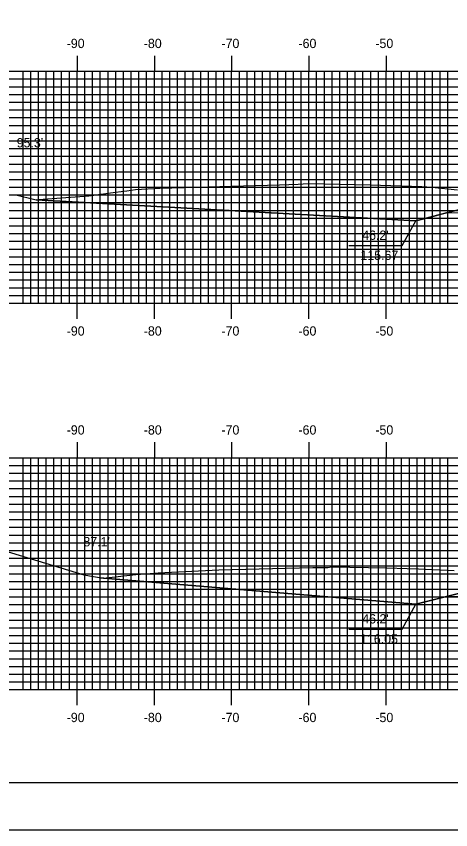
# Model space of a CAD drawing. Extents: x 854681 to 855024, y 366605 to 366825.
# Drawn here: x 854748.7 to 854804.9, y 366604.9 to 366710.2 of the extents above; entities that cross this region are included whole.
import ezdxf

# ---------------------------------------------------------------- set-up
doc = ezdxf.new("R2010")
doc.units = 0
for name, color, linetype in [('ANNOTATION', 7, 'Continuous'), ('BORDER', 7, 'Continuous'), ('D_Drainage_Underdrain', 7, 'Continuous'), ('D_Roadway_Centerline', 7, 'Continuous'), ('D_Roadway_SlopeLines', 7, 'Continuous'), ('D_Roadway_SubGrade', 7, 'Continuous'), ('D_Text_Standard', 7, 'Continuous'), ('H_V ANNOTATION', 7, 'Continuous'), ('M_Roadway_Centerline', 7, 'Continuous'), ('MAJOR', 7, 'Continuous'), ('MINOR', 7, 'Continuous'), ('PLOT BOUNDARY', 7, 'Continuous'), ('S_Roadway_Centerline', 7, 'Continuous')]:
    doc.layers.add(name, color=color, linetype=linetype)

msp = doc.modelspace()

# ---------------------------------------------------------------- linework, layer by layer
at = {"layer": 'ANNOTATION'}
for points in [[(854804.38, 366684.73), (854800.38, 366683.73), (854751.25, 366686.43)], [(854791.72, 366680.52), (854798.65, 366680.52), (854800.38, 366683.73)], [(854791.72, 366630.89), (854798.65, 366630.89), (854800.38, 366634.1)]]:
    msp.add_lwpolyline(points, dxfattribs=at)
at = {"layer": 'BORDER'}
msp.add_lwpolyline([(854696.96, 366611.06), (855016.96, 366611.06), (855016.96, 366821.06), (854696.96, 366821.06)], close=True, dxfattribs=at)
at = {"layer": 'D_Drainage_Underdrain'}
msp.add_lwpolyline([(854804.38, 366635.1), (854800.38, 366634.1), (854759.48, 366637.54)], dxfattribs=at)
at = {"layer": 'D_Roadway_Centerline'}
for points in [[(854751.25, 366686.43), (854751.26, 366686.43), (854800.38, 366683.73), (854802.76, 366684.32), (854803.66, 366684.55), (854810.24, 366686.2), (854814.56, 366687.27), (854816.02, 366687.33), (854822.55, 366687.59), (854822.56, 366687.59), (854822.56, 366687.59), (854834.56, 366687.83), (854846.56, 366688.07), (854848.89, 366687.99), (854850.56, 366687.92), (854851.62, 366687.78), (854854.63, 366687.37)], [(854759.48, 366637.54), (854759.49, 366637.54), (854800.38, 366634.1), (854803.66, 366634.92), (854803.66, 366634.92), (854814.56, 366637.65), (854814.56, 366637.65), (854818.67, 366637.81), (854822.56, 366637.97), (854834.55, 366638.21), (854834.56, 366638.21), (854846.55, 366638.45), (854846.56, 366638.45), (854850.56, 366638.29), (854852.3, 366638.08), (854855.81, 366637.66)]]:
    msp.add_lwpolyline(points, dxfattribs=at)
at = {"layer": 'D_Roadway_SlopeLines'}
for p, q in [((854814.56, 366687.27), (854800.38, 366683.73)), ((854800.38, 366683.73), (854751.25, 366686.43)), ((854800.38, 366634.1), (854759.48, 366637.54)), ((854814.56, 366637.65), (854800.38, 366634.1))]:
    msp.add_line(p, q, dxfattribs=at)
at = {"layer": 'D_Roadway_SubGrade'}
for points in [[(854822.56, 366686.93), (854822.56, 366687.34), (854814.56, 366687.02), (854814.56, 366687.27), (854804.38, 366684.73), (854822.56, 366685.09)], [(854822.56, 366637.3), (854822.56, 366637.72), (854814.56, 366637.4), (854814.56, 366637.65), (854804.38, 366635.1), (854822.56, 366635.47)]]:
    msp.add_lwpolyline(points, close=True, dxfattribs=at)
at = {"layer": 'MAJOR'}
for p, q in [((854756.56, 366705.06), (854756.56, 366703.06)), ((854766.56, 366705.06), (854766.56, 366703.06)), ((854776.56, 366705.06), (854776.56, 366703.06)), ((854786.56, 366705.06), (854786.56, 366703.06)), ((854796.56, 366705.06), (854796.56, 366703.06)), ((854706.56, 366703.06), (854986.56, 366703.06)), ((854706.56, 366703.06), (854986.56, 366703.06)), ((854756.56, 366673.06), (854756.56, 366703.06)), ((854766.56, 366673.06), (854766.56, 366703.06)), ((854776.56, 366673.06), (854776.56, 366703.06)), ((854786.56, 366673.06), (854786.56, 366703.06)), ((854796.56, 366673.06), (854796.56, 366703.06)), ((854706.56, 366698.06), (854986.56, 366698.06)), ((854706.56, 366693.06), (854986.56, 366693.06)), ((854706.56, 366688.06), (854986.56, 366688.06)), ((854706.56, 366683.06), (854986.56, 366683.06)), ((854706.56, 366678.06), (854986.56, 366678.06)), ((854706.56, 366673.06), (854986.56, 366673.06)), ((854706.56, 366673.06), (854986.56, 366673.06)), ((854756.56, 366671.05), (854756.56, 366673.06)), ((854766.56, 366671.05), (854766.56, 366673.06)), ((854776.56, 366671.05), (854776.56, 366673.06)), ((854786.56, 366671.05), (854786.56, 366673.06)), ((854796.56, 366671.05), (854796.56, 366673.06)), ((854756.56, 366655.06), (854756.56, 366653.06)), ((854766.56, 366655.06), (854766.56, 366653.06)), ((854776.56, 366655.06), (854776.56, 366653.06)), ((854786.56, 366655.06), (854786.56, 366653.06)), ((854796.56, 366655.06), (854796.56, 366653.06)), ((854706.56, 366653.06), (854986.56, 366653.06)), ((854706.56, 366653.06), (854986.56, 366653.06)), ((854756.56, 366623.06), (854756.56, 366653.06)), ((854766.56, 366623.06), (854766.56, 366653.06)), ((854776.56, 366623.06), (854776.56, 366653.06)), ((854786.56, 366623.06), (854786.56, 366653.06)), ((854796.56, 366623.06), (854796.56, 366653.06)), ((854706.56, 366648.06), (854986.56, 366648.06)), ((854706.56, 366643.06), (854986.56, 366643.06)), ((854706.56, 366638.06), (854986.56, 366638.06)), ((854706.56, 366633.06), (854986.56, 366633.06)), ((854706.56, 366628.06), (854986.56, 366628.06)), ((854706.56, 366623.06), (854986.56, 366623.06)), ((854706.56, 366623.06), (854986.56, 366623.06)), ((854756.56, 366621.05), (854756.56, 366623.06)), ((854766.56, 366621.05), (854766.56, 366623.06)), ((854776.56, 366621.05), (854776.56, 366623.06)), ((854786.56, 366621.05), (854786.56, 366623.06)), ((854796.56, 366621.05), (854796.56, 366623.06))]:
    msp.add_line(p, q, dxfattribs=at)
at = {"layer": 'MINOR'}
for p, q in [((854749.56, 366673.06), (854749.56, 366703.06)), ((854750.56, 366673.06), (854750.56, 366703.06)), ((854751.56, 366673.06), (854751.56, 366703.06)), ((854752.56, 366673.06), (854752.56, 366703.06)), ((854753.56, 366673.06), (854753.56, 366703.06)), ((854754.56, 366673.06), (854754.56, 366703.06)), ((854755.56, 366673.06), (854755.56, 366703.06)), ((854757.56, 366673.06), (854757.56, 366703.06)), ((854758.56, 366673.06), (854758.56, 366703.06)), ((854759.56, 366673.06), (854759.56, 366703.06)), ((854760.56, 366673.06), (854760.56, 366703.06)), ((854761.56, 366673.06), (854761.56, 366703.06)), ((854762.56, 366673.06), (854762.56, 366703.06)), ((854763.56, 366673.06), (854763.56, 366703.06)), ((854764.56, 366673.06), (854764.56, 366703.06)), ((854765.56, 366673.06), (854765.56, 366703.06)), ((854767.56, 366673.06), (854767.56, 366703.06)), ((854768.56, 366673.06), (854768.56, 366703.06)), ((854769.56, 366673.06), (854769.56, 366703.06)), ((854770.56, 366673.06), (854770.56, 366703.06)), ((854771.56, 366673.06), (854771.56, 366703.06)), ((854772.56, 366673.06), (854772.56, 366703.06)), ((854773.56, 366673.06), (854773.56, 366703.06)), ((854774.56, 366673.06), (854774.56, 366703.06)), ((854775.56, 366673.06), (854775.56, 366703.06)), ((854777.56, 366673.06), (854777.56, 366703.06)), ((854778.56, 366673.06), (854778.56, 366703.06)), ((854779.56, 366673.06), (854779.56, 366703.06)), ((854780.56, 366673.06), (854780.56, 366703.06)), ((854781.56, 366673.06), (854781.56, 366703.06)), ((854782.56, 366673.06), (854782.56, 366703.06)), ((854783.56, 366673.06), (854783.56, 366703.06)), ((854784.56, 366673.06), (854784.56, 366703.06)), ((854785.56, 366673.06), (854785.56, 366703.06)), ((854787.56, 366673.06), (854787.56, 366703.06)), ((854788.56, 366673.06), (854788.56, 366703.06)), ((854789.56, 366673.06), (854789.56, 366703.06)), ((854790.56, 366673.06), (854790.56, 366703.06)), ((854791.56, 366673.06), (854791.56, 366703.06)), ((854792.56, 366673.06), (854792.56, 366703.06)), ((854793.56, 366673.06), (854793.56, 366703.06)), ((854794.56, 366673.06), (854794.56, 366703.06)), ((854795.56, 366673.06), (854795.56, 366703.06)), ((854797.56, 366673.06), (854797.56, 366703.06)), ((854798.56, 366673.06), (854798.56, 366703.06)), ((854799.56, 366673.06), (854799.56, 366703.06)), ((854800.56, 366673.06), (854800.56, 366703.06)), ((854801.56, 366673.06), (854801.56, 366703.06)), ((854802.56, 366673.06), (854802.56, 366703.06)), ((854803.56, 366673.06), (854803.56, 366703.06)), ((854804.56, 366673.06), (854804.56, 366703.06)), ((854706.56, 366702.06), (854986.56, 366702.06)), ((854706.56, 366701.06), (854986.56, 366701.06)), ((854706.56, 366700.06), (854986.56, 366700.06)), ((854706.56, 366699.06), (854986.56, 366699.06)), ((854706.56, 366697.06), (854986.56, 366697.06)), ((854706.56, 366696.06), (854986.56, 366696.06)), ((854706.56, 366695.06), (854986.56, 366695.06)), ((854706.56, 366694.06), (854986.56, 366694.06)), ((854706.56, 366692.06), (854986.56, 366692.06)), ((854706.56, 366691.06), (854986.56, 366691.06)), ((854706.56, 366690.06), (854986.56, 366690.06)), ((854706.56, 366689.06), (854986.56, 366689.06)), ((854706.56, 366687.06), (854986.56, 366687.06)), ((854706.56, 366686.06), (854986.56, 366686.06)), ((854706.56, 366685.06), (854986.56, 366685.06)), ((854706.56, 366684.06), (854986.56, 366684.06)), ((854706.56, 366682.06), (854986.56, 366682.06)), ((854706.56, 366681.06), (854986.56, 366681.06)), ((854706.56, 366680.06), (854986.56, 366680.06)), ((854706.56, 366679.06), (854986.56, 366679.06)), ((854706.56, 366677.06), (854986.56, 366677.06)), ((854706.56, 366676.06), (854986.56, 366676.06)), ((854706.56, 366675.06), (854986.56, 366675.06)), ((854706.56, 366674.06), (854986.56, 366674.06)), ((854749.56, 366623.06), (854749.56, 366653.06)), ((854750.56, 366623.06), (854750.56, 366653.06)), ((854751.56, 366623.06), (854751.56, 366653.06)), ((854752.56, 366623.06), (854752.56, 366653.06)), ((854753.56, 366623.06), (854753.56, 366653.06)), ((854754.56, 366623.06), (854754.56, 366653.06)), ((854755.56, 366623.06), (854755.56, 366653.06)), ((854757.56, 366623.06), (854757.56, 366653.06)), ((854758.56, 366623.06), (854758.56, 366653.06)), ((854759.56, 366623.06), (854759.56, 366653.06)), ((854760.56, 366623.06), (854760.56, 366653.06)), ((854761.56, 366623.06), (854761.56, 366653.06)), ((854762.56, 366623.06), (854762.56, 366653.06)), ((854763.56, 366623.06), (854763.56, 366653.06)), ((854764.56, 366623.06), (854764.56, 366653.06)), ((854765.56, 366623.06), (854765.56, 366653.06)), ((854767.56, 366623.06), (854767.56, 366653.06)), ((854768.56, 366623.06), (854768.56, 366653.06)), ((854769.56, 366623.06), (854769.56, 366653.06)), ((854770.56, 366623.06), (854770.56, 366653.06)), ((854771.56, 366623.06), (854771.56, 366653.06)), ((854772.56, 366623.06), (854772.56, 366653.06)), ((854773.56, 366623.06), (854773.56, 366653.06)), ((854774.56, 366623.06), (854774.56, 366653.06)), ((854775.56, 366623.06), (854775.56, 366653.06)), ((854777.56, 366623.06), (854777.56, 366653.06)), ((854778.56, 366623.06), (854778.56, 366653.06)), ((854779.56, 366623.06), (854779.56, 366653.06)), ((854780.56, 366623.06), (854780.56, 366653.06)), ((854781.56, 366623.06), (854781.56, 366653.06)), ((854782.56, 366623.06), (854782.56, 366653.06)), ((854783.56, 366623.06), (854783.56, 366653.06)), ((854784.56, 366623.06), (854784.56, 366653.06)), ((854785.56, 366623.06), (854785.56, 366653.06)), ((854787.56, 366623.06), (854787.56, 366653.06)), ((854788.56, 366623.06), (854788.56, 366653.06)), ((854789.56, 366623.06), (854789.56, 366653.06)), ((854790.56, 366623.06), (854790.56, 366653.06)), ((854791.56, 366623.06), (854791.56, 366653.06)), ((854792.56, 366623.06), (854792.56, 366653.06)), ((854793.56, 366623.06), (854793.56, 366653.06)), ((854794.56, 366623.06), (854794.56, 366653.06)), ((854795.56, 366623.06), (854795.56, 366653.06)), ((854797.56, 366623.06), (854797.56, 366653.06)), ((854798.56, 366623.06), (854798.56, 366653.06)), ((854799.56, 366623.06), (854799.56, 366653.06)), ((854800.56, 366623.06), (854800.56, 366653.06)), ((854801.56, 366623.06), (854801.56, 366653.06)), ((854802.56, 366623.06), (854802.56, 366653.06)), ((854803.56, 366623.06), (854803.56, 366653.06)), ((854804.56, 366623.06), (854804.56, 366653.06)), ((854706.56, 366652.06), (854986.56, 366652.06)), ((854706.56, 366651.06), (854986.56, 366651.06)), ((854706.56, 366650.06), (854986.56, 366650.06)), ((854706.56, 366649.06), (854986.56, 366649.06)), ((854706.56, 366647.06), (854986.56, 366647.06)), ((854706.56, 366646.06), (854986.56, 366646.06)), ((854706.56, 366645.06), (854986.56, 366645.06)), ((854706.56, 366644.06), (854986.56, 366644.06)), ((854706.56, 366642.06), (854986.56, 366642.06)), ((854706.56, 366641.06), (854986.56, 366641.06)), ((854706.56, 366640.06), (854986.56, 366640.06)), ((854706.56, 366639.06), (854986.56, 366639.06)), ((854706.56, 366637.06), (854986.56, 366637.06)), ((854706.56, 366636.06), (854986.56, 366636.06)), ((854706.56, 366635.06), (854986.56, 366635.06)), ((854706.56, 366634.06), (854986.56, 366634.06)), ((854706.56, 366632.06), (854986.56, 366632.06)), ((854706.56, 366631.06), (854986.56, 366631.06)), ((854706.56, 366630.06), (854986.56, 366630.06)), ((854706.56, 366629.06), (854986.56, 366629.06)), ((854706.56, 366627.06), (854986.56, 366627.06)), ((854706.56, 366626.06), (854986.56, 366626.06)), ((854706.56, 366625.06), (854986.56, 366625.06)), ((854706.56, 366624.06), (854986.56, 366624.06))]:
    msp.add_line(p, q, dxfattribs=at)
at = {"layer": 'PLOT BOUNDARY'}
msp.add_lwpolyline([(854680.77, 366604.94), (855020.77, 366604.94), (855020.77, 366824.94), (854680.77, 366824.94)], close=True, dxfattribs=at)
at = {"layer": 'S_Roadway_Centerline'}
for points in [[(854748.62, 366687.09), (854751.07, 366686.48), (854751.25, 366686.43), (854751.58, 366686.46), (854758.06, 366686.94), (854761.55, 366687.42), (854762.99, 366687.61), (854764.12, 366687.77), (854767.25, 366687.92), (854782.75, 366688.37), (854785.15, 366688.46), (854785.83, 366688.48), (854786.54, 366688.53), (854794.47, 366688.35), (854801.18, 366688.14), (854802.48, 366688.08), (854805.78, 366687.71)], [(854745.03, 366641.68), (854757.44, 366637.9), (854759.95, 366637.46), (854764.15, 366637.94), (854766.6, 366638.11), (854767.04, 366638.18), (854774.9, 366638.55), (854774.9, 366638.55), (854774.92, 366638.55), (854787.07, 366638.84), (854789, 366638.88), (854789.49, 366638.93), (854796.64, 366638.8), (854799.26, 366638.73), (854800.73, 366638.67), (854805.37, 366638.49)]]:
    msp.add_lwpolyline(points, dxfattribs=at)

# ---------------------------------------------------------------- texts
at = {"layer": 'ANNOTATION'}
for s, p in [("46.2' ", (854793.46, 366681.25)), ('115.67', (854793.23, 366678.65)), ("46.2' ", (854793.46, 366631.62)), ('116.05', (854793.18, 366629.02))]:
    msp.add_text(s, height=1.2, rotation=360, dxfattribs=at).set_placement(p)
at = {"layer": 'D_Text_Standard'}
for s, p in [("95.3'", (854748.74, 366693.21)), ("87.1'", (854757.37, 366641.6))]:
    msp.add_text(s, height=1.2, dxfattribs=at).set_placement(p)
at = {"layer": 'H_V ANNOTATION'}
for s, p in [('-90', (854755.21, 366706.06)), ('-80', (854765.19, 366706.06)), ('-70', (854775.24, 366706.06)), ('-60', (854785.21, 366706.06)), ('-50', (854795.16, 366706.06)), ('-90', (854755.21, 366668.86)), ('-80', (854765.19, 366668.86)), ('-70', (854775.24, 366668.86)), ('-60', (854785.21, 366668.86)), ('-50', (854795.16, 366668.86)), ('-90', (854755.21, 366656.06)), ('-80', (854765.19, 366656.06)), ('-70', (854775.24, 366656.06)), ('-60', (854785.21, 366656.06)), ('-50', (854795.16, 366656.06)), ('-90', (854755.21, 366618.86)), ('-80', (854765.19, 366618.86)), ('-70', (854775.24, 366618.86)), ('-60', (854785.21, 366618.86)), ('-50', (854795.16, 366618.86))]:
    msp.add_text(s, height=1.2, dxfattribs=at).set_placement(p)
at = {"layer": 'M_Roadway_Centerline'}
for s, p in [('C', (854786.53, 366688.53)), ('L', (854786.54, 366688.52)), ('C', (854789.48, 366638.93)), ('L', (854789.49, 366638.92))]:
    msp.add_text(s, height=0.0146, dxfattribs=at).set_placement(p)

doc.saveas('drawing.dxf')
